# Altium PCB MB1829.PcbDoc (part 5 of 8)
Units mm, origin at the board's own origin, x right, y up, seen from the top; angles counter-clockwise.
Board outline 90 x 110 mm, 6 copper layers (Top Layer, Signal Layer 1, Signal Layer 2, Signal Layer 3, Signal Layer 4, Bottom Layer), stack 1.578 mm thick; 466 components, 354 nets, 2058 pads, 1522 vias.
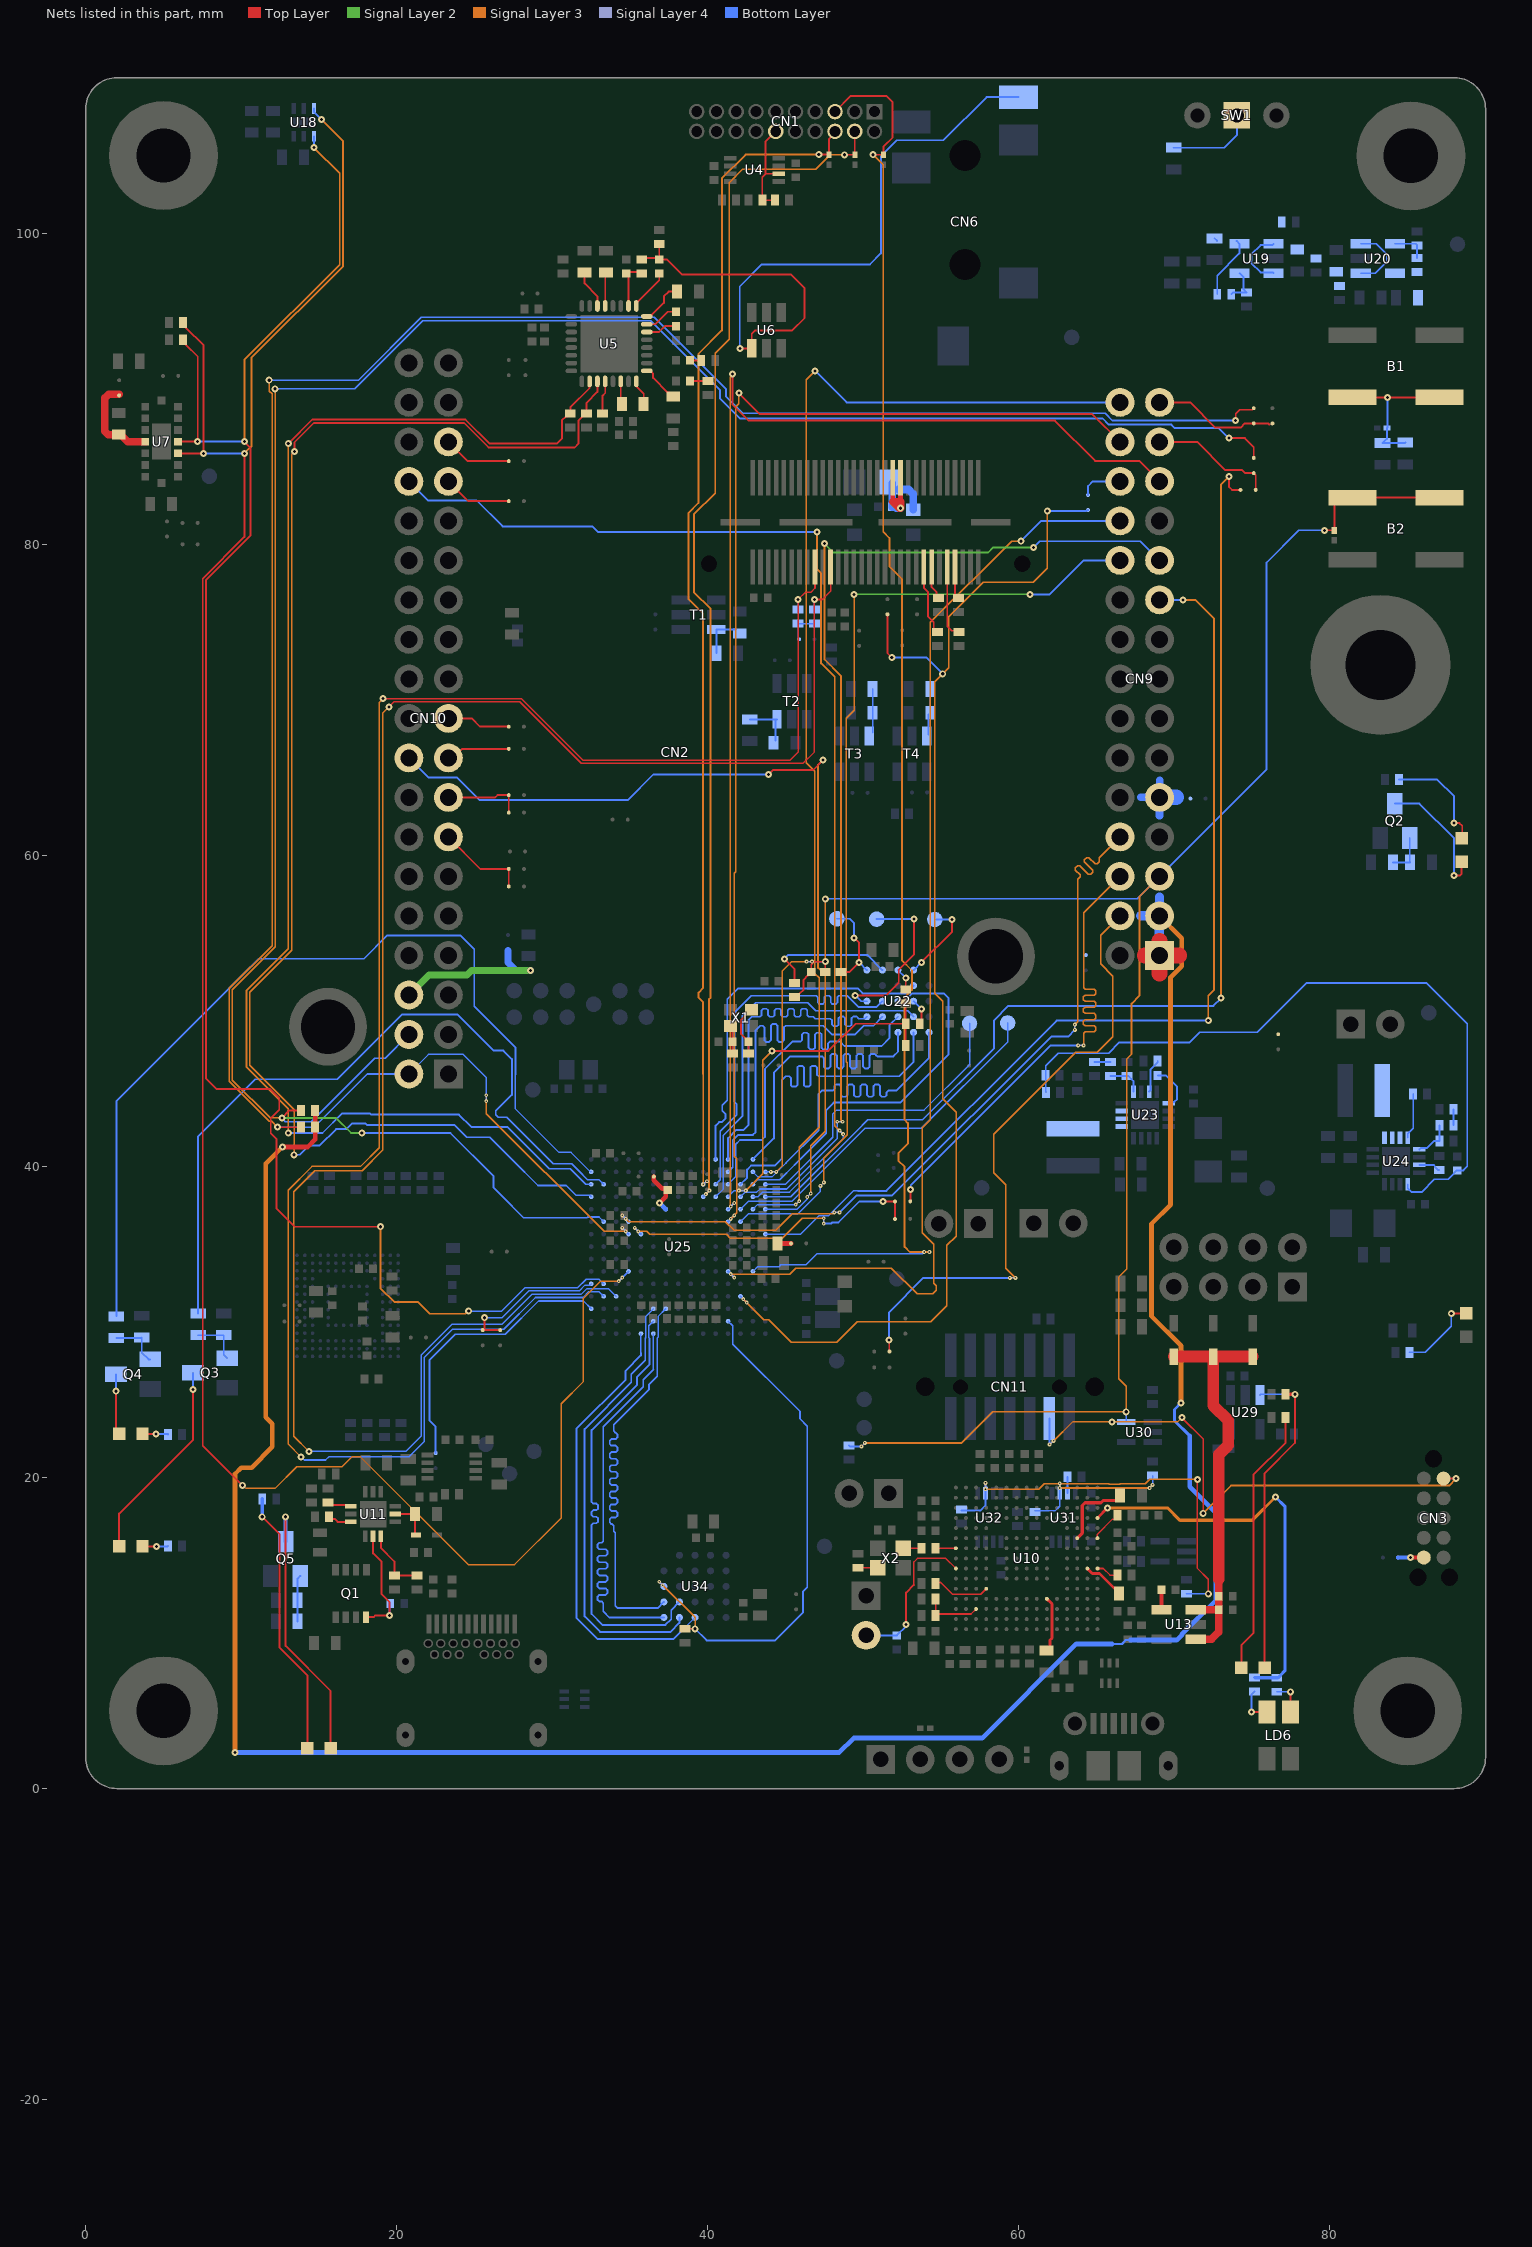
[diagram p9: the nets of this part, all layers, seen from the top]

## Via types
v1: diameter 0.45, hole 0.2, Top Layer to Bottom Layer, tented both sides, 1062 vias
v2: diameter 0.25, hole 0.1, Signal Layer 4 to Bottom Layer, tented both sides, 274 vias
v3: diameter 0.25, hole 0.1, Signal Layer 3 to Signal Layer 4, tented both sides, 119 vias
v4: diameter 0.25, hole 0.1, Top Layer to Signal Layer 1, tented both sides, 47 vias
v5: diameter 0.25, hole 0.1, Signal Layer 1 to Signal Layer 2, tented both sides, 20 vias

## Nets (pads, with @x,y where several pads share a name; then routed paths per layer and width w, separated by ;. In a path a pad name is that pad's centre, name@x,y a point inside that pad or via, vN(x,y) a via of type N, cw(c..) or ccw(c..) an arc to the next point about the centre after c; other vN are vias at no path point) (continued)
HEXASPI1.IO11: U25.G13 U34.A4 | length 28.8
  Bottom Layer w0.1: 36.75,26.525 36.75,28.975 36.8,29.025 36.8,30.35 U25.G13@37.3,30.85
  Bottom Layer w0.12: 33.95,16.585 33.95,16.555 34.05,16.455 34.05,11.75 34.2,11.6 36.775,11.6 U34.A4@37.175,12 ; 33.95,16.59 33.95,16.905 33.845,17.01 33.8,17.01 33.695,17.115 33.695,17.325 33.8,17.43 33.95,17.43 34.075,17.43 34.18,17.535 34.18,17.745 34.075,17.85 33.95,17.85 33.8,17.85 33.695,17.955 33.695,18.165 33.8,18.27 33.95,18.27 34.075,18.27 34.18,18.375 34.18,18.585 34.075,18.69 33.95,18.69 33.8,18.69 33.695,18.795 33.695,19.005 33.8,19.11 33.95,19.11 34.075,19.11 34.18,19.215 34.18,19.425 34.075,19.53 33.95,19.53 33.8,19.53 33.695,19.635 33.695,19.845 33.8,19.95 33.95,19.95 34.075,19.95 34.18,20.055 34.18,20.265 34.075,20.37 33.95,20.37 33.8,20.37 33.695,20.475 33.695,20.685 33.8,20.79 33.95,20.79 34.075,20.79 34.18,20.895 34.18,21.105 34.075,21.21 33.95,21.21 33.8,21.21 33.695,21.315 33.695,21.525 33.8,21.63 33.95,21.63 34.075,21.63 34.18,21.735 34.18,21.945 34.075,22.05 33.95,22.05 33.8,22.05 33.695,22.155 33.695,22.365 33.8,22.47 33.95,22.47 34.075,22.47 34.18,22.575 34.18,22.785 34.075,22.89 34.055,22.89 33.95,22.995 33.95,23.1 33.95,23.4 36.225,25.675 36.225,26 36.75,26.525
HEXASPI1.IO12: U25.F15 U34.A5 | length 27.8
  Bottom Layer w0.1: 36.5,26.925 U25.F15@36.5,29.25
  Bottom Layer w0.12: 36.5,26.925 35.85,26.275 35.85,25.85 33.275,23.275 33.275,16.45 33.275,15.915 33.17,15.81 33.02,15.81 32.915,15.705 32.915,15.495 33.02,15.39 33.275,15.39 33.439,15.39 33.544,15.285 33.544,15.075 33.439,14.97 33.275,14.97 33.02,14.97 32.915,14.865 32.915,14.655 33.02,14.55 33.275,14.55 33.439,14.55 33.544,14.445 33.544,14.235 33.439,14.13 33.275,14.13 33.02,14.13 32.915,14.025 32.915,13.815 33.02,13.71 33.275,13.71 33.439,13.71 33.544,13.605 33.544,13.395 33.439,13.29 33.275,13.29 33.02,13.29 32.915,13.185 32.915,12.975 33.02,12.87 33.275,12.87 33.439,12.87 33.544,12.765 33.544,12.555 33.439,12.45 33.275,12.45 33.02,12.45 32.915,12.345 32.915,12.135 33.02,12.03 33.17,12.03 33.275,11.925 33.275,11.61 33.275,11.4 33.675,11 U34.A5@37.175,11
HEXASPI1.IO13: U25.F14 U34.B4 | length 28.6
  Bottom Layer w0.1: 36.25,27.275 36.25,28.95 36.2,29 36.2,29.75 U25.F14@36.5,30.05
  Bottom Layer w0.12: 36.25,27.275 35.45,26.475 35.45,25.975 32.525,23.05 32.525,18.95 32.525,18.74 32.525,18.425 32.63,18.32 32.836,18.32 32.941,18.215 32.941,18.005 32.836,17.9 32.63,17.9 32.525,17.795 32.525,17.585 32.63,17.48 32.836,17.48 32.941,17.375 32.941,17.165 32.836,17.06 32.63,17.06 32.525,16.955 32.525,16.7 32.525,11.225 33.225,10.525 37.275,10.525 37.65,10.9 37.65,11.475 U34.B4@38.175,12
HEXASPI1.IO14: U25.F13 U34.B5 | length 28.7
  Bottom Layer w0.1: 35.975,27.55 35.975,28.95 36,28.975 36,30.35 U25.F13@36.5,30.85
  Bottom Layer w0.12: 35.975,27.55 35.076,26.651 35.076,26.112 32.075,23.111 32.075,11.075 33.075,10.075 37.6,10.075 38.175,10.65 U34.B5@38.175,11
HEXASPI1.IO15: U25.E15 U34.C5 | length 28.7
  Bottom Layer w0.1: 35.7,28.025 U25.E15@35.7,29.25
  Bottom Layer w0.12: 35.7,28.025 35.7,27.85 34.713,26.863 34.713,26.288 31.55,23.125 31.55,10.975 32.9,9.625 37.8,9.625 U34.C5@39.175,11
HEXASPI1.NCS: R52.1 U25.M14 U34.A3 | length 34
  Top Layer w0.12: R52.1@38.525,10.275 v1(39.175,10.275)
  Signal Layer 3 w0.09: v3(37.1,13.075) 39.175,11 v1(39.175,10.275)
  Signal Layer 4 w0.1: v2(36.875,13.3) v3(37.1,13.075)
  Bottom Layer w0.1: U25.M14@41.3,30.05 41.6,29.75 41.6,28.575
  Bottom Layer w0.12: v2(36.875,13.3) U34.A3@37.175,13 ; v1(39.175,10.275) 39.925,9.525 44.338,9.525 46.115,11.302 46.115,12.66 46.39,12.935 46.39,23.31 45.925,23.775 45.925,24.25 41.6,28.575
I2C1.SCL: CN10.2 R29.1 SB7.1 U25.D7 | length 152
  Top Layer w0.09: v1(12.325,42.525) R29.1@13.85,42.525 ; v1(73.925,87.95) 73.945,87.97 73.945,88.395 74.2,88.65 74.994,88.65 75.094,88.75 SB7.1@75.1,88.75
  Signal Layer 3 w0.09: v1(11.8,90.55) 11.805,90.545 11.805,89.847 11.985,89.667 11.985,54.204 9.235,51.454 9.235,45.471 11.812,42.894 11.956,42.894 v1(12.325,42.525) ; v3(25.75,44.2) 25.75,43.4 33.325,35.825 v3(34.725,35.825)
  Signal Layer 4 w0.1: v3(25.75,44.2) v2(25.75,44.575) ; v2(34.5,36.05) v3(34.725,35.825)
  Bottom Layer w0.1: v1(12.325,42.525) 14.675,42.525 18.094,45.944 CN10.2@20.78,45.944 22.036,47.2 24.266,47.2 25.75,45.716 v2(25.75,44.575)
  Bottom Layer w0.12: v1(11.8,90.55) 17.539,90.55 21.584,94.595 36.564,94.595 41.175,89.984 41.175,89.502 42.253,88.424 65.544,88.424 66.018,87.95 v1(73.925,87.95) ; v2(34.5,36.05) U25.D7@34.9,35.65
I2C1.SDA: CN10.4 R28.1 SB8.1 U25.B6 | length 154.9
  Top Layer w0.12: v1(12.625,43.125) 13.1,43.6 R28.1@13.85,43.6 ; v1(73.5,86.825) 74.525,86.825 75.1,86.25 SB8.1@75.1,85.55
  Signal Layer 2 w0.12: v1(12.625,43.125) 16.088,43.125 17.063,42.15 v1(17.75,42.15)
  Signal Layer 3 w0.09: v1(12.175,90) 12.175,54.125 9.425,51.375 9.425,45.55 11.85,43.125 v1(12.625,43.125)
  Bottom Layer w0.1: 27.425,37.431 28.156,36.7 32.225,36.7 32.275,36.75 33,36.75 U25.B6@33.3,36.45
  Bottom Layer w0.12: v1(12.175,90) 17.3,90 21.675,94.375 36.325,94.375 40.775,89.925 40.775,89.391 42.066,88.1 65.375,88.1 65.775,87.7 69.8,87.7 70.025,87.475 72.85,87.475 v1(73.5,86.825) ; v1(12.625,43.125) 12.625,43.075 12.825,42.875 14.5,42.875 18.585,46.96 19.256,46.96 CN10.4@20.78,48.484 ; v1(17.75,42.15) 23.45,42.15 26.225,39.375 26.225,38.631 27.425,37.431
I2C3.SCL: R8.1 U7.C4 U18.1 U25.B11 | length 116.3
  Top Layer w0.12: U7.C4@5.925,86.6 v1(7.2,86.6) 7.2,92.075 6.445,92.83 6.445,92.955 R8.1@6.25,93.15 ; v1(10.2,86.6) 10.585,86.215 10.585,80.549 7.745,77.709 7.745,45.647 8.417,44.975 11.861,44.975 12.441,44.396 12.441,43.641 11.9,43.1 11.9,42.125 12.255,41.77 12.255,37.298 13.428,36.125 v1(18.95,36.125)
  Signal Layer 3 w0.12: v1(10.2,86.6) 10.2,91.853 16.33,97.983 16.33,103.855 v1(14.675,105.51) ; v1(18.95,36.125) 18.95,32.184 19.859,31.275 21.375,31.275 22.125,30.525 24.39,30.525 24.565,30.7 v1(24.625,30.7)
  Bottom Layer w0.1: v1(24.625,30.7) 26.75,30.7 28.25,32.2 31.625,32.2 32.175,32.75 33,32.75 U25.B11@33.3,32.45
  Bottom Layer w0.12: v1(7.2,86.6) v1(10.2,86.6) ; v1(14.675,105.51) U18.1@14.675,106.235
I2C3.SDA: R7.1 U7.C3 U18.6 U25.D10 | length 151.2
  Top Layer w0.12: U7.C3@5.925,85.85 v1(7.575,85.85) 7.575,86.431 7.585,86.441 7.585,92.79 6.445,93.93 6.445,94.055 R7.1@6.25,94.25 ; v1(10.075,19.5) 7.525,22.05 7.525,77.8 10.2,80.475 v1(10.2,85.85)
  Signal Layer 3 w0.1: v1(10.075,19.5) 10.109,19.5 10.309,19.3 12.175,19.3 13.575,20.7 16.475,20.7 17.1,21.325 17.675,21.325 24.6,14.4 27.575,14.4 30.575,17.4 30.575,24.75 32.003,26.178 32.003,31.52 32.95,32.467 32.95,32.474 33.101,32.625 v3(34.275,32.625)
  Signal Layer 3 w0.12: v1(10.2,85.85) 10.65,86.3 10.65,91.992 16.55,97.892 16.55,105.925 v1(15.15,107.325)
  Signal Layer 4 w0.1: v3(34.275,32.625) v2(34.5,32.85)
  Bottom Layer w0.12: v1(7.575,85.85) v1(10.2,85.85) ; U18.6@14.675,108.015 14.675,107.8 v1(15.15,107.325) ; v2(34.5,32.85) U25.D10@34.9,33.25
I2C4.SCL: R14.1 U5.3 U25.A4 | length 94.2
  Top Layer w0.12: v1(13.425,85.975) 13.425,86.564 14.661,87.8 24.328,87.8 25.903,86.225 31.43,86.225 31.675,86.47 31.675,87.95 31.917,88.192 31.917,88.205 32.112,88.4 R14.1@32.207,88.4 32.207,89.1 ; 32.203,89.103 32.9,89.8 U5.3@32.9,90.475
  Signal Layer 3 w0.12: v1(13.4,40.75) 13.41,40.76 13.41,43.64 10.55,46.5 10.55,51.2 13.245,53.895 13.245,85.795 v1(13.425,85.975)
  Bottom Layer w0.1: 27.425,40.425 29.075,38.775 30.9,38.775 31.525,38.15 32.4,38.15 U25.A4@32.5,38.05
  Bottom Layer w0.12: v1(13.4,40.75) 13.775,40.75 14.375,41.35 15.047,41.35 16.102,42.405 16.744,42.405 16.808,42.468 16.818,42.468 17.105,42.755 18.001,42.755 18.081,42.675 23.689,42.675 24.484,41.88 25.97,41.88 27.425,40.425
I2C4.SDA: R13.1 U5.2 U25.A3 | length 91.9
  Top Layer w0.12: v1(13.025,86.475) 14.575,88.025 24.415,88.025 25.965,86.475 30.3,86.475 30.619,86.794 30.619,87.969 30.855,88.205 30.955,88.205 R13.1@31.15,88.4 31.165,88.415 31.165,88.815 32.4,90.05 U5.2@32.4,90.475
  Signal Layer 3 w0.12: v1(13.025,42.15) 13.025,43.7 10.775,45.95 10.775,45.964 10.33,46.409 10.33,51.291 13.025,53.986 v1(13.025,86.475)
  Bottom Layer w0.1: 27.425,42.225 29.8,39.85 31.15,39.85 32.15,38.85 U25.A3@32.5,38.85
  Bottom Layer w0.12: v1(13.025,42.15) 15.225,42.15 16.49,43.415 18.274,43.415 18.354,43.335 23.99,43.335 24.785,42.54 27.11,42.54 27.425,42.225
I2C5.SCL: CN2.44 R70.2 U25.B12 | length 122.5
  Top Layer w0.1: v1@19.125,70.079 27.996,70.079 31.95,66.125 45.3,66.125 45.8,66.625 v1(45.8,76.45) 46.275,76.925 46.625,76.925 46.889,77.189 CN2.44@46.889,78.54
  Signal Layer 3 w0.1: v1(13.85,21.325) 13.025,22.15 13.025,38.475 14.55,40 17.675,40 18.88,41.205 18.88,69.83 v1(19.125,70.075)
  Bottom Layer w0.1: v1(13.85,21.325) 14.05,21.125 15.425,21.125 15.625,21.325 20.775,21.325 21.76,22.31 21.76,27.71 23.575,29.525 26.87,29.525 28.92,31.575 31.975,31.575 32.35,31.95 33,31.95 U25.B12@33.3,31.65 ; R70.2@45.8,75.796 v1(45.8,76.45)
I2C5.SDA: CN2.40 R69.2 U25.C12 | length 122.6
  Top Layer w0.1: v1(19.5,69.55) 19.829,69.879 27.913,69.879 31.867,65.925 46.125,65.925 46.85,66.65 v1(46.85,76.45) 47.35,76.45 47.889,76.989 CN2.40@47.889,78.54
  Signal Layer 3 w0.1: v1(14.353,21.675) 13.375,22.653 13.375,38.375 14.725,39.725 17.775,39.725 19.1,41.05 19.1,69.15 v1(19.5,69.55)
  Bottom Layer w0.1: v1(14.353,21.675) 20.575,21.675 21.56,22.66 21.56,27.86 23.55,29.85 26.76,29.85 28.685,31.775 31.85,31.775 32.225,32.15 32.45,32.15 33.6,32.15 U25.C12@34.1,31.65 ; R69.2@46.85,75.796 v1(46.85,76.45)
IOREF: CN9.3 R28.2 R29.2 SB56.2 | length 163.3
  Top Layer w0.3: v1(12.64,41.25) 14.265,41.25 14.75,41.735 R29.2@14.75,42.525 R28.2@14.75,43.6
  Signal Layer 3 w0.3: v1(9.6,2.325) 9.6,20.225 10.008,20.633 10.662,20.633 12,21.971 12,23.45 11.575,23.875 11.575,40.185 v1(12.64,41.25) ; CN9.3@69.04,56.104 70.47,54.674 70.47,52.875 69.75,52.155 69.75,37.55 68.525,36.325 68.525,30.375 70.425,28.475 v1(70.425,24.8)
  Bottom Layer w0.15: 66,9.3 66.625,9.3 66.875,9.55 67.175,9.55
  Bottom Layer w0.2: v1(70.425,24.8) 70,24.375 70,23.65 70.975,22.675
  Bottom Layer w0.3: v1(9.6,2.325) 48.45,2.325 49.375,3.25 57.633,3.25 63.683,9.3 66,9.3 ; 67.175,9.55 70.15,9.55 70.5,9.9 ; v1(70.425,24.8) v1@70.425,24.825 ; 70.475,9.925 72.675,12.125 72.675,17.7 70.975,19.4 70.975,22.675
  Bottom Layer w0.6: 67.825,56.125 69.019,56.125 CN9.3@69.04,56.104 ; 69.019,54.91 CN9.3@69.019,56.104 ; CN9.3@69.04,56.125 69.04,57.319
IOVDD_TOF_SENSOR: C18.1 SB5.2 U7.A4 | length 6
  Top Layer w0.5: SB5.2@2.15,89.65 1.475,89.65 1.225,89.4 1.225,87.275 1.45,87.05 2.25,87.05 2.7,86.6 U7.A4@3.825,86.6
LED_GREEN: R107.1 U25.A2 | length 59.5
  Bottom Layer w0.1: 27.625,45.925 27.625,43.7 30.425,40.9 31.209,40.9 32.459,39.65 U25.A2@32.5,39.65
  Bottom Layer w0.12: R107.1@1.972,30.366 1.972,44.191 11.131,53.35 17.892,53.35 19.392,54.85 24.084,54.85 24.978,53.957 24.978,50.298 27.635,47.64 27.635,45.935 27.625,45.925
LED_RED: R105.1 U25.B3 | length 48.8
  Bottom Layer w0.1: 31.944,39.47 32.265,39.15 33,39.15 U25.B3@33.3,38.85
  Bottom Layer w0.12: R105.1@7.225,30.55 7.225,41.94 10.891,45.606 16.173,45.606 20.342,49.775 23.9,49.775 26.225,47.45 26.85,47.45 27.4,46.9 27.4,44.603 26.365,43.568 26.365,43.332 26.532,43.165 27.085,43.165 30.075,40.175 31.24,40.175 31.944,39.47
LED_STLK: R130.2 R131.2 U10.D15 | length 26.3
  Top Layer w0.2: U10.D15@65.05,17.4 v1(65.7,18.05)
  Signal Layer 3 w0.2: v1(65.7,18.05) 69.55,18.05 70.35,17.25 75,17.25 v1(76.5,18.75)
  Bottom Layer w0.2: R130.2@75.15,7.15 75.175,7.125 76.67,7.125 76.825,7.28 76.825,7.3 77.1,7.575 77.1,18.15 v1(76.5,18.75)
MEMS_LED: CN1.12 R2.2 R3.2 U4.2 | length 6.5
  Top Layer w0.12: R3.2@44.325,102.125 R2.2@43.5,102.125 43.5,103.604 43.7,103.804 ; CN1.12@44.365,106.55 43.7,105.885 43.7,103.804 ; U4.2@44.55,103.825 43.721,103.825 43.7,103.804
MIC: C6.1 CN6.2 R4.2 R6.1 U6.4 | length 50.2
  Top Layer w0.12: R6.1@35.75,98.4 36.875,98.4 R4.2@36.875,99.3 ; C6.1@36.875,98.3 37.375,98.3 38.325,97.35 45.325,97.35 46.225,96.45 46.225,94.55 45.428,93.753 43.053,93.753 42.825,93.525 42.825,93.425 ; v1(42.055,92.6) U6.4@42.825,92.6 42.825,93.425
  Bottom Layer w0.12: v1(42.055,92.6) 42.055,94.545 42.05,94.55 42.05,96.575 43.475,98 50.425,98 51.125,98.7 51.125,104.95 52.15,105.975 55.15,105.975 57.925,108.75 CN6.2@59.975,108.75
MIC.CCK0: CN1.4 U2.1 U25.K4 | length 77.7
  Top Layer w0.12: v1(48.779,105.046) U2.1@49.441,105.046 ; CN1.4@49.445,106.55 49.445,105.043 U2.1@49.45,105.037
  Signal Layer 3 w0.1: v3(39.875,38.225) 40.075,38.425 40.075,45.925
  Signal Layer 3 w0.12: 40.075,45.925 40.075,50.763 40.172,50.861 40.172,75.853 39.108,76.917 39.108,81.922 40.475,83.289 40.475,92.275 41.375,93.175 41.375,103.261 42.229,104.115 46.926,104.115 47.857,105.046 v1(48.779,105.046)
  Signal Layer 4 w0.1: v3(39.875,38.225) v2(40.1,38.45)
  Bottom Layer w0.12: U25.K4@39.7,38.05 v2(40.1,38.45)
MIC.SDIN0: CN1.6 U1.1 U25.K3 | length 76.1
  Top Layer w0.12: v1(47.131,105.056) U1.1@47.794,105.056 ; U1.1@47.8,105.037 47.8,106.063 48.175,106.438 CN1.6@48.175,106.55
  Signal Layer 3 w0.1: v3(39.7,38.85) 39.7,45.925
  Signal Layer 3 w0.12: 39.7,45.925 39.7,50.563 39.402,50.861 39.402,51.179 39.7,51.477 39.7,75.548 38.75,76.497 38.75,82.012 39.4,82.662 39.4,92.25 40.9,93.75 40.9,103.525 42.431,105.056 v1(47.131,105.056)
  Signal Layer 4 w0.1: v3(39.7,38.85) 39.723,38.85 39.924,39.051 v2(39.947,39.051)
  Bottom Layer w0.1: v3(39.7,38.85) 39.723,38.85 39.924,39.051 v2(39.947,39.051)
MIC.SDIN4: CN1.5 U3.1 U25.P10 | length 94.2
  Top Layer w0.12: CN1.5@48.175,107.82 49.19,108.835 51.466,108.835 51.875,108.426 51.875,106.156 51.3,105.581 U3.1@51.3,105.037 51.287,105.05 v1(50.625,105.05)
  Signal Layer 3 w0.12: v1(50.625,105.05) 51.28,104.395 51.28,80.8 51.675,80.406 51.675,78.584 52.475,77.784 52.475,53.248 53.125,52.598 53.125,51.35 52.652,50.877 52.652,43 52.864,42.789 52.864,41.464 52.25,40.85 52.25,40.379 52.65,39.979 52.65,34.83 52.98,34.5 v3(54.248,34.5)
  Signal Layer 4 w0.1: v2(53.9,34.5) v3(54.248,34.5)
  Bottom Layer w0.1: U25.P10@42.9,33.25 43.2,33.55 44.567,33.55 44.692,33.675 46.309,33.675 47.034,34.4 50.796,34.4 53.8,34.4 v2(53.9,34.5)
NetB1_1: B1.1 B1.2 R67.2 R68.2 U21.1 | length 10.1
  Top Layer w0.12: B1.2@81.45,89.45 v1(83.688,89.45) B1.1@87.05,89.45
  Bottom Layer w0.12: R68.2@83.375,86.515 R68.2@83.402,86.515 ; v1(83.688,89.45) 83.688,87.501 U21.1@83.662,87.475 83.662,86.775 R68.2@83.402,86.515 ; R67.2@84.85,86.54 84.825,86.515 R68.2@83.402,86.515
NetC3_2: C3.2 U5.22 | length 2.5
  Top Layer w0.12: C3.2@32.075,97.475 32.075,96.775 32.9,95.95 U5.22@32.9,95.325
NetC4_2: C4.2 U5.21 | length 2.2
  Top Layer w0.12: U5.21@33.4,95.325 33.4,97.425 C4.2@33.45,97.475
NetC5_2: C5.2 R6.2 U5.18 | length 3.2
  Top Layer w0.12: U5.18@34.9,95.325 34.9,97.35 34.75,97.5 R6.2@35.75,97.5
NetC6_2: C6.2 U5.17 | length 2.8
  Top Layer w0.12: U5.17@35.4,95.325 35.4,95.5 36.875,96.975 C6.2@36.875,97.5
NetC7_2: C7.2 U5.16 | length 2.9
  Top Layer w0.12: U5.16@36.075,94.65 36.3,94.65 37.175,95.525 37.175,95.95 37.475,96.25 C7.2@38.025,96.25
NetC9_2: C9.2 U5.15 | length 2.2
  Top Layer w0.12: U5.15@36.075,94.15 36.625,94.15 37.425,94.95 C9.2@37.95,94.95
NetC10_2: C10.2 U5.14 | length 2
  Top Layer w0.12: U5.14@36.075,93.65 36.85,93.65 37.225,94.025 C10.2@37.95,94.025
NetC14_1: C14.1 R10.2 | length 0.8
  Top Layer w0.12: C14.1@38.825,91.825 R10.2@39.575,91.825
NetC15_1: C15.1 R11.2 | length 1.2
  Top Layer w0.12: C15.1@38.825,90.5 R11.2@40,90.5
NetC16_2: C16.2 U5.9 | length 2.5
  Top Layer w0.12: U5.9@36.075,91.15 36.3,91.15 36.48,90.97 36.48,90.695 37.425,89.75 37.525,89.75 C16.2@37.775,89.5
NetC17_1: C17.1 U5.8 | length 1.6
  Top Layer w0.12: U5.8@35.4,90.475 35.4,90.15 35.875,89.675 C17.1@35.875,89.025
NetC17_2: C17.2 U5.6 | length 1.5
  Top Layer w0.12: U5.6@34.4,90.475 34.4,89.1 C17.2@34.475,89.025
NetC32_1: C32.1 R27.2 X1.3 | length 1.8
  Top Layer w0.12: X1.3@41.45,49.025 41.575,48.9 C32.1@41.575,48.025 R27.2@41.575,47.25
NetC33_1: C33.1 R26.2 X1.1 | length 3.3
  Top Layer w0.12: R26.2@42.625,47.25 C33.1@42.625,48.025 42.125,48.525 42.125,49.4 X1.1@42.8,50.075
NetC38_2: C38.2 SB32.2 U25.G5 | length 2.9
  Top Layer w0.3: SB32.2@36.525,39.35 36.525,39.114 37.059,38.58 37.295,38.58 37.295,38.045 v1@36.9,37.65
  Bottom Layer w0.3: v1(36.9,37.65) U25.G5@37.3,37.25
NetC78_2: C78.2 U10.F13 | length 5.1
  Top Layer w0.2: U10.F13@63.75,16.1 64.075,16.425 64.075,18.2 64.25,18.375 65.275,18.375 65.425,18.525 66.5,18.525 C78.2@66.5,18.85
NetC81_2: C81.2 D4.2 U11.8 | length 2.6
  Top Layer w0.12: U11.8@19.9,17.65 C81.2@21.175,17.65 21.175,16.35 D4.2@21.225,16.3
NetC95_2: C95.2 U10.J14 | length 2.8
  Top Layer w0.2: U10.J14@64.4,14.15 64.725,13.825 65.15,13.825 65.185,13.825 66.115,12.895 66.205,12.895 66.425,12.675 C95.2@66.425,12.55
NetC96_2: C96.2 U13.4 | length 1.3
  Top Layer w0.25: U13.4@69.175,11.5 C96.2@69.175,12.775
NetC98_2: C98.2 C100.2 D1.2 D2.2 D3.2 U13.1 U13.3 | length 26.6
  Top Layer w0.5: U13.1@71.375,9.6 72.375,9.6 72.85,10.075 C100.2@72.85,11.5 ; U13.3@71.375,11.5 C100.2@72.85,11.5 ; 72.85,13.45 C98.2@72.85,12.375 C100.2@72.85,11.5
  Top Layer w0.75: D2.2@69.95,27.78 D1.2@72.5,27.78 ; 72.85,13.45 72.85,21.475 73.45,22.075 73.45,23.675 72.5,24.625 D1.2@72.5,27.78 ; D3.2@75.025,27.78 D1.2@72.5,27.78
NetC110_2: C110.2 U10.M10 | length 3.6
  Top Layer w0.2: C110.2@61.775,8.85 62,9.075 62,9.55 62.125,9.675 62.125,11.875 U10.M10@61.8,12.2
NetC115_2: C115.2 R57.2 R61.2 U19.1 U19.3 | length 4
  Bottom Layer w0.12: U19.3@76.375,97.425 76.317,97.483 75.542,97.483 74.95,98.075 74.95,98.65 75.542,99.242 76.292,99.242 U19.1@76.375,99.325
NetC116_2: C116.2 R63.2 U20.1 U20.3 | length 4.4
  Bottom Layer w0.12: U20.1@81.975,97.425 82.9,97.425 83.65,98.175 83.65,98.65 82.975,99.325 U20.3@81.975,99.325
NetC119_1: C119.1 C120.2 CN2.21 CN2.23 L4.2 | length 8.4
  Top Layer w0.3: 51.885,82.738 CN2.23@51.885,84.097 ; 52.385,82.738 CN2.21@52.385,84.097
  Top Layer w0.5: 51.885,82.738 52.385,82.738 52.385,82.33 v1(52.376,82.321) 52.301,82.321 51.885,82.738
  Bottom Layer w0.5: C119.1@51.85,83.921 C120.2@51.85,82.421 51.85,82.396 51.855,82.391 52.061,82.391 52.131,82.321 v1@52.35,82.321 ; C119.1@52.25,83.521 52.907,83.521 53.2,83.229 L4.2@53.2,82.225
NetC121_1: C121.1 R73.2 T1.3 | length 2.8
  Bottom Layer w0.12: R73.2@40.55,72.996 T1.3@40.55,74.521 C121.1@41.8,74.521
NetC122_1: C122.1 R74.2 T4.3 | length 2.8
  Bottom Layer w0.12: T4.3@54.175,67.771 C122.1@54.175,69.046 ; C122.1@54.3,69.171 R74.2@54.3,70.696
NetC123_1: C123.1 R75.2 T3.3 | length 2.8
  Bottom Layer w0.12: T3.3@50.6,67.896 C123.1@50.6,69.171 R75.2@50.6,70.696
NetC124_1: C124.1 R76.2 T2.3 | length 3
  Bottom Layer w0.12: R76.2@42.7,68.746 T2.3@44.45,68.746 ; C124.1@44.35,67.371 T2.3@44.35,68.646
NetC126_2: C126.2 U23.9 | length 3
  Bottom Layer w0.12: C126.2@68.922,45.841 69.463,45.841 70.172,45.132 70.172,44.333 69.993,44.154 69.712,44.154 U23.9@69.622,44.064
NetC147_1: C147.1 Q1.4 U11.5 | length 7.9
  Top Layer w0.12: Q1.4@18.025,11.025 18.513,11.025 18.625,11.138 v1(19.525,11.138) 19.525,12 19.025,12.5 19.025,14.575 18.475,15.125 U11.5@18.475,16.225
  Bottom Layer w0.12: v1(19.525,11.138) 19.525,11.847 C147.1@19.578,11.9
NetC148_1: C148.1 JP6.2 U10.J1 | length 10.2
  Top Layer w0.1: 53.25,13.1 53.25,14.575 53.475,14.8 55.3,14.8 U10.J1@55.95,14.15
  Top Layer w0.12: v1(52.75,10.55) 52.75,12.6 53.25,13.1
  Bottom Layer w0.12: JP6.2@50.175,9.855 50.18,9.85 C148.1@52.15,9.85 52.75,10.45 v1(52.75,10.55)
NetC149_2: C149.2 R85.1 R87.1 U24.9 | length 46.2
  Bottom Layer w0.12: R87.1@61.747,44.766 61.722,44.791 R85.1@61.722,45.866 61.722,46.478 62.519,47.275 65.761,47.275 66.461,47.975 70.975,47.975 71.625,48.625 75.325,48.625 78.5,51.8 86.2,51.8 88.825,49.175 88.825,39.999 88.576,39.75 88.15,39.75 87.955,39.555 87.955,39.53 87.6,39.175 86.706,39.175 85.886,38.355 85.249,38.355 85.094,38.51 85.09,38.51 85,38.6 U24.9@85,38.85
NetCN2_8: CN2.8 R17.1 | length 2.1
  Top Layer w0.12: CN2.8@55.889,78.54 55.889,76.745 56.084,76.55 R17.1@56.125,76.55
NetCN2_10: CN2.10 R18.1 | length 4.7
  Top Layer w0.12: CN2.10@55.389,78.54 55.389,74.744 55.69,74.443 56.082,74.443 R18.1@56.15,74.375
NetCN2_14: CN2.14 R16.1 | length 2.2
  Top Layer w0.12: CN2.14@54.389,78.54 54.389,77.236 54.71,76.915 54.71,76.665 R16.1@54.825,76.55
NetCN2_16: CN2.16 R19.1 | length 4.6
  Top Layer w0.12: CN2.16@53.889,78.54 53.889,77.211 54.15,76.95 54.15,75.375 54.525,75 54.525,74.545 54.72,74.35 R19.1@54.775,74.35
NetCN3_5: CN3.5 SB61.2 | length 1.7
  Top Layer w0.25: v1(85.175,14.855) CN3.5@86.03,14.855
  Bottom Layer w0.25: SB61.2@84.375,14.85 84.727,14.85 84.732,14.855 v1(85.175,14.855)
NetCN9_1: CN9.1 SB26.2 | length 4.3
  Top Layer w1: 68.089,53.564 CN9.1@69.04,53.564 ; 69.04,52.405 CN9.1@69.04,53.564 ; 69.04,54.5 CN9.1@69.04,53.564 ; 70.296,53.564 CN9.1@69.04,53.564
NetCN9_4: CN9.4 SB45.1 | length 40.2
  Top Layer w0.12: v1(51.65,28.85) 51.663,28.837 51.663,28.113 SB45.1@51.675,28.1
  Signal Layer 3 w0.09: v3(59.77,32.83) 59.155,33.445 59.155,38.835 58.385,39.605 58.385,42.065 63.655,47.335 65.035,47.335 66.045,48.345 66.045,52.24 65.26,53.025 65.26,54.864 CN9.4@66.5,56.104
  Signal Layer 4 w0.1: v2(59.42,32.83) v3(59.77,32.83)
  Bottom Layer w0.12: v1(51.65,28.85) 51.65,30.625 53.855,32.83 v2(59.42,32.83)
NetCN9_6: CN9.6 SB33.1 | length 33
  Top Layer w0.12: SB33.1@53.013,37.75 53.024,37.761 53.024,38.499 v1(53.035,38.51)
  Signal Layer 3 w0.09: v3(64.157,47.783) 64.157,48.131 64.157,48.566 64.255,48.664 64.834,48.664 64.931,48.761 64.931,48.956 64.834,49.054 64.25,49.054 64.152,49.151 64.152,49.346 64.25,49.444 64.834,49.444 64.931,49.541 64.931,49.736 64.834,49.834 64.25,49.834 64.152,49.931 64.152,50.126 64.25,50.224 64.834,50.224 64.931,50.321 64.931,50.516 64.834,50.614 64.25,50.614 64.152,50.711 64.152,50.906 64.25,51.004 64.834,51.004 64.931,51.101 64.931,51.296 64.834,51.394 64.255,51.394 64.157,51.491 64.157,51.95 64.157,56.301 CN9.6@66.5,58.644
  Signal Layer 4 w0.1: v2(63.81,47.783) v3(64.157,47.783)
  Bottom Layer w0.12: v1(53.035,38.51) 53.045,38.52 53.045,38.795 62.033,47.783 v2(63.81,47.783)
NetCN9_9: CN9.9 SB54.2 | length 4.6
  Top Layer w0.7: CN9.9@69.04,63.724 CN9.9@69.114,63.651
  Bottom Layer w0.5: 67.85,63.734 CN9.9@69.04,63.734 ; 69.04,62.55 CN9.9@69.04,63.724 69.05,63.734 69.05,64.825
  Bottom Layer w1: CN9.9@69.05,63.724 70.125,63.724
NetCN9_26: CN9.26 SB48.1 | length 2.7
  Bottom Layer w0.12: SB48.1@64.45,83.175 64.45,83.75 64.744,84.044 CN9.26@66.5,84.044
NetCN9_27: CN9.27 SB8.2 SB9.2 | length 8
  Top Layer w0.12: CN9.27@69.04,86.584 71.466,86.584 73.275,84.775 74.35,84.775 74.55,84.575 SB8.2@75.1,84.575 75.1,84.561 75.225,84.436 SB9.2@75.225,83.5
NetCN9_29: CN9.29 SB6.2 SB7.2 | length 7.9
  Top Layer w0.12: CN9.29@69.04,89.124 71.001,89.124 72.625,87.5 74.25,87.5 74.525,87.775 SB7.2@75.1,87.775 76.025,87.775 76.103,87.697
NetCN10_6: CN10.6 SB55.1 | length 10.9
  Signal Layer 2 w0.45: CN10.6@20.78,51.024 22.07,52.314 24.509,52.314 24.795,52.6 v1(28.6,52.6)
  Bottom Layer w0.45: SB55.1@27.15,53.9 27.15,53.116 27.666,52.6 v1(28.6,52.6)
NetCN10_13: CN10.13 SB24.2 SB25.2 | length 5.9
  Top Layer w0.12: CN10.13@23.32,61.184 25.379,59.125 SB24.2@27.2,59.125 SB25.2@27.2,58
NetCN10_15: CN10.15 SB22.2 SB23.2 | length 5.1
  Top Layer w0.12: CN10.15@23.32,63.724 26.324,63.724 26.475,63.875 SB22.2@27.2,63.875 SB23.2@27.2,62.75
NetCN10_17: CN10.17 SB21.2 | length 4.1
  Top Layer w0.12: CN10.17@23.32,66.264 23.611,66.264 24.197,66.85 SB21.2@27.2,66.85
NetCN10_19: CN10.19 SB20.2 | length 4.1
  Top Layer w0.12: CN10.19@23.32,68.804 24.821,68.804 25.35,68.275 SB20.2@27.2,68.275
NetCN10_31: CN10.31 SB11.2 | length 4.4
  Top Layer w0.12: CN10.31@23.32,84.044 24.589,82.775 SB11.2@27.2,82.775
NetCN10_33: CN10.33 SB10.2 | length 4.4
  Top Layer w0.12: CN10.33@23.32,86.584 24.554,85.35 SB10.2@27.2,85.35
NetL2_1: L2.1 SB36.2 | length 0.9
  Top Layer w0.3: L2.1@44.475,35.05 SB36.2@45.35,35.05
NetL6_1: L6.1 U24.1 U24.2 U24.3
NetL7_1: L7.1 U23.1 U23.2 U23.3
NetLD1_1: LD1.1 R77.1 | length 7.2
  Top Layer w0.12: v1(87.975,62.075) 88.325,62.075 88.5,61.9 LD1.1@88.5,61
  Bottom Layer w0.12: R77.1@84.446,64.879 85.37,64.879 85.372,64.876 86.899,64.876 87.975,63.8 v1(87.975,62.075)
NetLD1_2: LD1.2 Q2.3 | length 8.4
  Top Layer w0.12: v1(87.975,58.7) 88.35,58.7 88.45,58.8 88.45,59.575 LD1.2@88.475,59.6
  Bottom Layer w0.12: Q2.3@84.175,63.325 85.75,63.325 87.975,61.1 v1(87.975,58.7)
NetLD2_1: LD2.1 R109.1 | length 5.2
  Top Layer w0.12: v1(87.8,30.55) LD2.1@88.75,30.55
  Bottom Layer w0.12: R109.1@85.1,28.05 86.131,28.05 87.8,29.719 v1(87.8,30.55)
NetLD3_1: LD3.1 R116.1 | length 1.7
  Top Layer w0.12: LD3.1@3.65,22.8 v1(4.525,22.8)
  Bottom Layer w0.12: v1(4.525,22.8) 5.275,22.8 R116.1@5.3,22.775
NetLD3_2: LD3.2 Q4.3 | length 3.9
  Top Layer w0.12: v1(1.95,25.55) 1.95,23 LD3.2@2.15,22.8
  Bottom Layer w0.12: Q4.3@1.947,26.641 1.947,25.553 v1(1.95,25.55)
NetLD4_1: LD4.1 R125.1 | length 1.7
  Top Layer w0.12: LD4.1@3.65,15.575 v1(4.55,15.575)
  Bottom Layer w0.12: v1(4.55,15.575) 5.275,15.575 R125.1@5.3,15.6
NetLD4_2: LD4.2 Q3.3 | length 13.1
  Top Layer w0.12: LD4.2@2.15,15.575 2.15,17.675 6.9,22.425 v1(6.9,25.65)
  Bottom Layer w0.12: v1(6.9,25.65) Q3.3@6.9,26.725
NetLD5_1: LD5.1 R34.1 | length 17.3
  Top Layer w0.12: LD5.1@74.3,7.775 74.3,9.225 75.075,10 75.075,20.175 77.15,22.25 R34.1@77.15,23.85
NetLD5_2: LD5.2 R33.1 U29.3 | length 21.3
  Top Layer w0.12: LD5.2@75.8,7.775 75.8,20.275 77.75,22.225 v1(77.75,25.35)
  Top Layer w0.2: R33.1@77.15,25.35 v1(77.75,25.35)
  Bottom Layer w0.12: U29.3@75.5,25.3 75.55,25.35 v1(77.75,25.35)
NetLD6_1: LD6.1 R130.1 | length 2.4
  Top Layer w0.12: v1@74.95,4.936 74.961,4.925 LD6.1@75.95,4.925
  Bottom Layer w0.12: v1(74.955,4.93) 74.955,6.055 R130.1@75.15,6.25
NetLD6_2: LD6.2 R131.1 | length 2.2
  Top Layer w0.12: LD6.2@77.45,4.925 v1(77.45,6.225)
  Bottom Layer w0.12: R131.1@76.575,6.225 v1(77.45,6.225)
NetLD7_1: LD7.1 R120.1 | length 17.2
  Top Layer w0.12: v1(11.35,17.475) 12.45,16.375 12.45,9.075 14.25,7.275 LD7.1@14.25,2.6
  Bottom Layer w0.25: v1(11.35,17.475) R120.1@11.35,18.625
NetLD7_2: LD7.2 Q5.3 | length 17.7
  Top Layer w0.12: v1(12.85,17.475) 12.85,9.175 15.75,6.275 LD7.2@15.75,2.6
  Bottom Layer w0.25: Q5.3@12.85,15.875 v1(12.85,17.475)
NetQ2_1: Q2.1 R79.2 R80.2 | length 2.7
  Bottom Layer w0.12: R80.2@84.05,59.55 R79.2@85.15,59.55 85.125,59.575 Q2.1@85.125,61.125
NetQ3_1: Q3.1 R104.2 R105.2 | length 3.2
  Bottom Layer w0.12: R105.2@7.225,29.15 R104.2@8.875,29.15 8.875,27.9 Q3.1@9.1,27.675
NetQ4_1: Q4.1 R106.2 R107.2 | length 3.3
  Bottom Layer w0.12: R107.2@1.972,28.966 3.566,28.966 R106.2@3.6,29 3.6,28.031 4.04,27.591 Q4.1@4.147,27.591
NetQ5_1: Q5.1 R128.2 R129.2 | length 3
  Bottom Layer w0.12: R129.2@13.625,10.75 R128.2@13.625,12.1 13.625,13.5 Q5.1@13.8,13.675
NetR12_1: R12.1 U5.4 | length 2.1
  Top Layer w0.12: R12.1@33.225,88.4 33.231,88.406 33.231,89.559 33.4,89.729 U5.4@33.4,90.475
NetR21_1: R21.1 TP4.1 U22.A5 | length 6
  Top Layer w0.12: R21.1@48.55,52.5 49.1,52.5 v1(49.725,53.125) 49.725,54.375 v1(49.4,54.7)
  Bottom Layer w0.12: TP4.1@48.3,55.925 49.125,55.925 49.4,55.65 v1(49.4,54.7) ; v1(49.725,53.125) U22.A5@50.225,52.625
NetR22_2: R22.2 U22.A4 | length 8.6
  Top Layer w0.12: v1(44.925,53.35) 45.567,52.708 R22.2@45.567,51.805
  Bottom Layer w0.12: v1(44.925,53.35) 45.174,53.599 50.251,53.599 U22.A4@51.225,52.625
NetR23_1: R23.1 U22.A3 | length 1.5
  Top Layer w0.12: R23.1@52.725,51.375 v1(52.725,52.125)
  Bottom Layer w0.12: U22.A3@52.225,52.625 v1(52.725,52.125)
NetR24_2: R24.2 U22.C2 | length 1.7
  Top Layer w0.12: R24.2@53.625,49.175 53.725,49.275 v1(53.725,50.125)
  Bottom Layer w0.12: U22.C2@53.225,50.625 v1(53.725,50.125)
NetR40_2: R40.2 U11.1 | length 1.6
  Top Layer w0.12: R40.2@15.575,18.4 15.75,18.225 16.975,18.225 U11.1@17.05,18.15
NetR42_1: R42.1 U10.F15 | length 2.2
  Top Layer w0.1: U10.F15@65.05,16.1 65.05,16.36 66.015,17.325 66.35,17.325 R42.1@66.35,17.575
NetR43_2: R43.2 U11.3 | length 1.5
  Top Layer w0.12: R43.2@15.65,17.475 15.79,17.335 16.015,17.335 16.2,17.15 U11.3@17.05,17.15
NetR44_1: R44.1 X2.3 | length 1.2
  Top Layer w0.1: 53.175,15.45 R44.1@53.75,15.45
  Top Layer w0.12: X2.3@52.575,15.45 53.175,15.45
NetR44_2: R44.2 U10.G1 | length 1.3
  Top Layer w0.1: R44.2@54.65,15.45 U10.G1@55.95,15.45
NetR45_2: R45.2 X2.1 | length 1.3
  Top Layer w0.12: R45.2@49.65,14.2 X2.1@50.925,14.2
NetR46_2: R46.2 U10.J15 | length 1.5
  Top Layer w0.1: U10.J15@65.05,14.15 65.425,14.15 65.85,13.725 R46.2@66.35,13.725
NetR47_1: R47.1 R48.1 U11.6 | length 4.3
  Top Layer w0.12: U11.6@18.975,16.225 18.975,15.475 19.85,14.6 R47.1@19.85,13.7 R48.1@21.3,13.7
NetR49_2: R49.2 U10.L4 | length 3.7
  Top Layer w0.1: R49.2@54.65,13.25 54.975,13.25 55.725,12.5 57.55,12.5 U10.L4@57.9,12.85
NetR50_1: R50.1 R51.1 U10.N3 | length 3.9
  Top Layer w0.1: R50.1@54.65,12.2 R51.1@54.65,11.125 54.75,11.225 56.925,11.225 U10.N3@57.25,11.55
NetR55_2: R55.2 SW1.1 | length 5.7
  Bottom Layer w0.12: R55.2@69.95,105.5 73.213,105.5 74.015,106.302 SW1.1@74.015,107.575
NetR58_2: R58.2 R60.1 U20.4 | length 2.3
  Bottom Layer w0.12: U20.4@84.175,99.325 85.5,99.325 R58.2@85.6,99.225 85.6,98.409 R60.1@85.591,98.4
NetR59_1: R59.1 R65.2 U19.5 | length 4.3
  Bottom Layer w0.12: R59.1@72.575,99.675 R59.1@72.742,99.508 ; R65.2@72.75,96.075 72.75,97.275 74.175,98.7 U19.5@74.175,99.325 U19.5@73.992,99.508
NetR60_2: R60.2 R66.1 U20.5
NetR64_2: R64.2 R65.1 U19.4 | length 2.5
  Bottom Layer w0.12: R65.1@73.65,96.075 73.775,96.2 R64.2@74.625,96.2 74.441,96.384 74.441,97.185 74.201,97.425 U19.4@74.175,97.425
NetR69_1: R69.1 R70.1 SB50.1 | length 2
  Bottom Layer w0.1: SB50.1@45.8,73.971 R70.1@45.8,74.896 R69.1@46.85,74.896
NetR81_2: R81.2 U23.7 | length 2.2
  Bottom Layer w0.12: U23.7@68.372,44.814 68.45,44.892 68.45,46.225 R81.2@68.726,46.501 ; R81.2@68.727,46.501 68.922,46.696 R81.2@68.922,46.791
NetR82_2: R82.2 R83.1 U23.5 | length 2.3
  Bottom Layer w0.12: R83.1@65.897,45.816 R82.2@66.947,45.816 67.042,45.816 R82.2@67.237,45.621 ; R82.2@67.237,45.62 67.372,45.485 U23.5@67.372,44.814
NetR83_2: R83.2 R84.2 | length 1.1
  Bottom Layer w0.12: R84.2@64.847,46.716 R83.2@65.897,46.716
NetR88_1: R88.1 U24.4 | length 2.9
  Bottom Layer w0.12: U24.4@85,41.85 85,42.1 85.09,42.19 85.35,42.45 R88.1@85.35,44.65
NetR89_1: R89.1 R90.2 | length 1
  Bottom Layer w0.12: R90.2@87.95,42.65 R89.1@87.95,43.675
NetR90_1: R90.1 R91.2 U24.5 | length 2.5
  Bottom Layer w0.12: U24.5@85.75,41.1 85.832,41.182 86.233,41.182 86.676,41.625 R91.2@87.05,41.625 R90.1@87.05,42.65
NetR93_2: R93.2 U24.7 | length 1.4
  Bottom Layer w0.12: U24.7@85.75,40.1 86.665,40.1 86.735,40.03 86.735,39.97 86.93,39.775 R93.2@87.025,39.775
NetR118_2: R118.2 R122.1 U31.6 | length 10.2
  Signal Layer 3 w0.1: v3(62.625,19.325) v3(68.4,19.325)
  Signal Layer 4 w0.1: v3(62.625,19.325) v2(62.625,19.625) ; v3(68.4,19.325) v2(68.6,19.525)
  Bottom Layer w0.1: R122.1@61.025,17.85 62.325,17.85 62.625,18.15 U31.6@62.625,18.975 v2(62.625,19.625) ; v2(68.6,19.525) R118.2@68.6,20.125
NetR119_2: R119.2 U31.7 | length 1.1
  Bottom Layer w0.1: U31.7@63.125,18.975 R119.2@63.125,20.05
NetR121_1: R121.1 R127.2 U32.6 | length 26.5
  Top Layer w0.1: v1(71.475,19.875) 71.475,14.155 72.175,13.455 v1(72.175,12.525)
  Signal Layer 3 w0.09: v3(57.85,19.255) 61.28,19.255 61.62,19.595 65.762,19.595 65.802,19.555 66.483,19.555 66.513,19.585 68.11,19.585 68.4,19.875 v1(71.475,19.875)
  Signal Layer 4 w0.1: v3(57.85,19.255) v2(57.85,19.65)
  Bottom Layer w0.1: R127.2@70.775,12.525 v1(72.175,12.525)
  Bottom Layer w0.12: R121.1@56.3,17.875 57.525,17.875 57.85,18.2 U32.6@57.85,18.975 v2(57.85,19.65)
NetTP5_1: TP5.1 U22.C5 | length 10.9
  Top Layer w0.12: v1(49.475,51) 51.459,51 52.275,51.816 52.275,52.65 53.25,53.625 v1(53.25,55.9)
  Bottom Layer w0.12: v1(49.475,51) 49.85,50.625 U22.C5@50.225,50.625 ; TP5.1@50.85,55.9 v1(53.25,55.9)
NetTP6_1: TP6.1 U22.A2 | length 5.4
  Top Layer w0.12: v1(53.725,53.125) 55.7,55.1 v1(55.7,55.875)
  Bottom Layer w0.12: U22.A2@53.225,52.625 v1(53.725,53.125) ; TP6.1@54.592,55.879 54.596,55.875 v1(55.7,55.875)
NRST: B2.1 B2.2 C28.2 CN3.10 CN9.5 CN11.12 R20.1 R22.1 R117.1 U8.1 U25.R2 U30.5 | length 175.8
  Top Layer w0.1: C28.2@46.65,52.5 46.65,52.975 46.85,53.175 v1(47.55,53.175) ; v1(70.475,23.85) 71.85,22.475 v1(71.85,17.7)
  Top Layer w0.12: R22.1@45.567,50.905 45.762,51.1 45.892,51.1 46.152,51.361 46.152,52.002 46.43,52.28 46.43,52.305 46.625,52.5 C28.2@46.65,52.5 ; R20.1@47.55,52.5 v1(47.55,53.175) ; v1(79.65,80.9) 80.262,80.9 U8.1@80.275,80.887 80.3,80.912 80.3,82.775 80.525,83 B2.1@81.45,83 B2.2@87.05,83 ; CN3.10@87.3,19.935 87.31,19.925 v1(88.1,19.925)
  Signal Layer 3 w0.1: v3(44.398,39.65) 44.775,40.027 44.775,52.555 45.395,53.175 v3(46.35,53.175) ; v3(62.235,22.36) 63.45,23.575 v1(65.975,23.575) 70.2,23.575 v1(70.475,23.85) ; v1(66.9,24.225) 66.9,25.875 66.425,26.35 66.425,32.9 66.928,33.403 66.928,46.903 67.25,47.225
  Signal Layer 3 w0.12: v1(47.55,53.175) v1(47.55,57.2) ; v3(50.1,22.225) 56.315,22.225 58.315,24.225 v1(66.9,24.225) ; 67.25,47.225 67.25,50.475 67.75,50.975 67.75,57.354 CN9.5@69.04,58.644 ; v1(71.85,17.7) 73.635,19.485 87.66,19.485 v1(88.1,19.925)
  Signal Layer 4 w0.1: v2(44.05,39.65) v3(44.398,39.65) ; v3(46.35,53.175) v2(46.698,53.175) ; v2(49.875,22) v3(50.1,22.225) ; v2(61.975,22.125) 61.987,22.125 62.222,22.36 v3(62.235,22.36)
  Bottom Layer w0.1: U25.R2@43.7,39.65 v2(44.05,39.65) ; v2(46.698,53.175) v1(47.55,53.175) ; v1(65.975,23.575) U30.5@66.9,23.575 v1(66.9,24.225)
  Bottom Layer w0.12: v1(47.55,57.2) 47.56,57.21 67.606,57.21 75.93,65.534 75.93,78.83 78,80.9 v1(79.65,80.9) ; R117.1@49.075,22.05 49.125,22 v2(49.875,22) ; CN11.12@61.965,23.793 61.975,23.783 v2(61.975,22.125)
OCTOSPIM_P1.CLK: U22.B2 U25.L1 | length 23.5
  Bottom Layer w0.12: U25.L1@40.5,40.45 40.5,42.629 40.721,42.85 40.9,42.85 41.125,43.075 41.125,43.375 40.925,43.575 40.925,43.931 41.25,44.256 41.25,50.75 41.95,51.45 49.625,51.45 49.95,51.125 52.725,51.125 U22.B2@53.225,51.625
OCTOSPIM_P1.DQS: U22.C3 U25.P3 | length 24.1
  Bottom Layer w0.1: U25.P3@42.9,38.85 43.2,39.15 44.625,39.15 45.575,40.1
  Bottom Layer w0.12: 45.575,40.1 47.6,42.125 47.6,43.62 48.08,44.1 52.375,44.1 55.475,47.2 55.475,50.825 55.175,51.125 53.15,51.125 52.65,50.625 U22.C3@52.225,50.625
OCTOSPIM_P1.IO0: U22.D3 U25.M3 | length 23.6
  Bottom Layer w0.1: U25.M3@41.3,38.85 41.8,39.35 41.8,41.43 42.07,41.7
  Bottom Layer w0.12: 42.07,41.7 43.475,41.7 43.675,41.9 43.675,46.275 45.425,48.025 45.635,48.025 45.95,48.025 46.055,48.13 46.055,48.494 46.16,48.599 46.37,48.599 46.475,48.494 46.475,48.025 46.475,47.632 46.58,47.527 46.79,47.527 46.895,47.632 46.895,48.025 46.895,48.494 47,48.599 47.21,48.599 47.315,48.494 47.315,48.025 47.315,47.622 47.42,47.517 47.63,47.517 47.735,47.622 47.735,47.92 47.84,48.025 48.175,48.025 48.5,48.025 48.785,47.74 51.165,47.74 51.675,48.25 51.675,49.075 U22.D3@52.225,49.625
OCTOSPIM_P1.IO1: U22.D2 U25.L4 | length 24.1
  Bottom Layer w0.1: U25.L4@40.5,38.05 41,38.55 41,42 41.103,42.103
  Bottom Layer w0.12: 41.103,42.103 42.225,43.225 42.225,49.675 43.075,50.525 46.435,50.525 46.95,50.01 52.84,50.01 U22.D2@53.225,49.625
OCTOSPIM_P1.IO2: U22.C4 U25.L3 | length 23.7
  Bottom Layer w0.1: U25.L3@40.5,38.85 40.8,39.15 40.8,42.275
  Bottom Layer w0.12: 40.8,42.275 41.85,43.325 41.85,44 41.725,44.125 41.725,49.9 42.8,50.975 46.475,50.975 46.646,50.975 46.961,50.975 47.066,50.87 47.066,50.54 47.171,50.435 47.381,50.435 47.486,50.54 47.486,50.87 47.591,50.975 47.801,50.975 47.906,50.87 47.906,50.54 48.011,50.435 48.221,50.435 48.326,50.54 48.326,50.87 48.431,50.975 48.746,50.975 48.956,50.975 49.691,50.24 50.84,50.24 U22.C4@51.225,50.625
OCTOSPIM_P1.IO3: U22.D4 U25.M2 | length 23.3
  Bottom Layer w0.1: U25.M2@41.3,39.65 41.6,39.95 41.6,41.675
  Bottom Layer w0.12: 41.6,41.675 41.95,42.025 42.9,42.025 43.075,42.2 43.075,48.75 43.375,49.05 43.425,49.05 43.53,49.05 43.635,48.945 43.635,48.115 43.74,48.01 43.95,48.01 44.055,48.115 44.055,49.05 44.055,49.06 44.16,49.165 44.37,49.165 44.475,49.06 44.475,49.05 44.475,48.115 44.58,48.01 44.79,48.01 44.895,48.115 44.895,48.945 45,49.05 45.175,49.05 47.425,49.05 48,48.475 49.45,48.475 50.025,49.05 50.65,49.05 U22.D4@51.225,49.625
OCTOSPIM_P1.IO4: U22.D5 U25.M1 | length 22.7
  Bottom Layer w0.12: U25.M1@41.3,40.45 41.3,41.825 41.825,42.35 42.3,42.35 42.625,42.675 42.625,45.925 42.625,49.425 42.825,49.625 43.035,49.625 43.35,49.625 43.455,49.73 43.455,50.035 43.56,50.14 43.77,50.14 43.875,50.035 43.875,49.73 43.98,49.625 44.19,49.625 44.295,49.73 44.295,50.035 44.4,50.14 44.61,50.14 44.715,50.035 44.715,49.73 44.82,49.625 45.03,49.625 45.135,49.73 45.135,50.035 45.24,50.14 45.45,50.14 45.555,50.035 45.555,49.73 45.66,49.625 45.87,49.625 45.975,49.73 45.975,50.035 46.08,50.14 46.29,50.14 46.395,50.035 46.395,49.73 46.5,49.625 46.6,49.625 46.775,49.625 46.9,49.5 47.775,49.5 47.88,49.5 47.985,49.395 47.985,49.115 48.09,49.01 48.3,49.01 48.405,49.115 48.405,49.5 48.405,49.535 48.51,49.64 48.72,49.64 48.825,49.535 48.825,49.5 48.825,49.115 48.93,49.01 49.14,49.01 49.245,49.115 49.245,49.5 49.245,49.535 49.35,49.64 49.56,49.64 49.665,49.535 49.7,49.5 49.875,49.5 50.1,49.5 U22.D5@50.225,49.625
OCTOSPIM_P1.IO5: U22.E3 U25.P1 | length 22.3
  Bottom Layer w0.12: U25.P1@42.9,40.45 44.25,41.8 44.25,46.025 45.3,47.075 47.25,47.075 47.355,47.075 47.46,46.97 47.46,46.408 47.565,46.303 47.775,46.303 47.88,46.408 47.88,47.075 47.88,47.127 47.985,47.232 48.195,47.232 48.3,47.127 48.3,47.075 48.3,46.408 48.405,46.303 48.615,46.303 48.72,46.408 48.72,47.075 48.72,47.127 48.825,47.232 49.035,47.232 49.14,47.127 49.14,47.075 49.14,46.408 49.245,46.303 49.455,46.303 49.56,46.408 49.56,47.075 49.56,47.127 49.665,47.232 49.875,47.232 49.98,47.127 49.98,47.075 49.98,46.408 50.085,46.303 50.295,46.303 50.4,46.408 50.4,47.075 50.4,47.127 50.505,47.232 50.715,47.232 50.82,47.127 50.82,47.159 ; 50.82,47.16 50.905,47.075 51.55,47.075 51.925,47.075 52.225,47.375 U22.E3@52.225,48.625
OCTOSPIM_P1.IO6: U22.E2 U25.N3 | length 24.3
  Bottom Layer w0.12: U25.N3@42.1,38.85 42.525,39.275 42.525,39.8 42.775,40.05 44.3,40.05 44.775,40.525 44.775,45.575 45,45.8 45.175,45.8 45.23,45.8 45.335,45.695 45.335,45.235 45.44,45.13 45.65,45.13 45.755,45.235 45.755,45.8 45.755,46.365 45.86,46.47 46.07,46.47 46.175,46.365 46.175,45.8 46.175,45.235 46.28,45.13 46.49,45.13 46.595,45.235 46.595,45.8 46.595,46.365 46.7,46.47 46.91,46.47 47.015,46.365 47.015,45.905 47.12,45.8 47.225,45.8 52.3,45.8 53.225,46.725 U22.E2@53.225,48.625
OCTOSPIM_P1.IO7: U22.E1 U25.P2 | length 22.9
  Bottom Layer w0.1: U25.P2@42.9,39.65 43.2,39.35 44.15,39.35 45.025,40.225
  Bottom Layer w0.12: 45.025,40.225 47.125,42.325 47.125,44.675 47.325,44.875 48.03,44.875 48.135,44.98 48.135,45.167 48.24,45.272 48.45,45.272 48.555,45.167 48.555,44.875 48.555,44.583 48.66,44.478 48.87,44.478 48.975,44.583 48.975,44.875 48.975,45.167 49.08,45.272 49.29,45.272 49.395,45.167 49.395,44.875 49.395,44.583 49.5,44.478 49.71,44.478 49.815,44.583 49.815,44.875 49.815,45.167 49.92,45.272 50.13,45.272 50.235,45.167 50.235,44.875 50.235,44.583 50.34,44.478 50.55,44.478 50.655,44.583 50.655,44.875 50.655,45.167 50.76,45.272 50.97,45.272 51.075,45.167 51.075,44.875 51.075,44.583 51.18,44.478 51.39,44.478 51.495,44.583 51.495,44.77 51.6,44.875 51.915,44.875 52.125,44.875 54.225,46.975 U22.E1@54.225,48.625
OCTOSPIM_P1.NCS: R23.2 R24.1 R25.1 U25.M4 | length 23
  Top Layer w0.12: v1(44.125,47.425) 47.75,47.425 49.5,49.175 R24.1@52.725,49.175 ; R25.1@52.725,47.775 R24.1@52.725,49.175 ; R23.2@52.725,50.475 R24.1@52.725,49.175
  Signal Layer 3 w0.09: v3(42.45,38.45) 43.525,39.525 43.525,46.825 v1(44.125,47.425)
  Signal Layer 4 w0.1: v2(42,38.45) v3(42.45,38.45)
  Bottom Layer w0.1: U25.M4@41.3,38.05 41.7,38.45 v2(42,38.45)
OPAMP1_VINM: TP20.1 U25.R3 | length 19.8
  Bottom Layer w0.1: U25.R3@43.7,38.85 45,38.85 48.025,41.875 48.025,43.375 48.275,43.625 53.905,43.625 56.825,46.545 TP20.1@56.825,49.2
OPAMP2_VINM: TP19.1 U25.N5 | length 22.9
  Bottom Layer w0.1: U25.N5@42.1,37.25 42.6,37.75 45.4,37.75 50.1,42.45 53.725,42.45 59.275,48 TP19.1@59.275,49.225
PA0: CN9.21 U25.N4 | length 69.4
  Signal Layer 2 w0.12: v1(47.5,80.05) 48.076,79.474 58.024,79.474 58.355,79.805 v1(60.939,79.805)
  Signal Layer 3 w0.12: v1(47.5,80.05) 47.5,72.6 48.55,71.55 48.55,45.925 48.55,42.99 v3(48.665,42.875)
  Signal Layer 4 w0.1: v2(48.317,42.875) v3(48.665,42.875)
  Bottom Layer w0.1: U25.N4@42.1,38.05 42.4,38.35 43.15,38.35 43.35,38.55 45.075,38.55 48.317,41.792 v2(48.317,42.875)
  Bottom Layer w0.12: v1(60.939,79.805) 61.334,80.2 67.804,80.2 CN9.21@69.04,78.964
PA3: CN10.32 U25.P4 | length 74.6
  Signal Layer 3 w0.12: v1(47.025,80.8) 47.025,78.393 47.28,78.138 47.28,72.346 48.155,71.471 48.155,45.925 48.155,42.62 v3(48.475,42.3)
  Signal Layer 4 w0.1: v3(48.475,42.3) v2(48.7,42.075)
  Bottom Layer w0.1: U25.P4@42.9,38.05 43.225,38.05 43.525,38.35 45.258,38.35 48.7,41.792 v2(48.7,42.075)
  Bottom Layer w0.12: CN10.32@20.78,84.044 21.999,82.825 25.125,82.825 26.8,81.15 32.578,81.15 32.928,80.8 v1(47.025,80.8)
PA4: CN9.25 U25.M5 | length 86
  Top Layer w0.12: v1(41.575,90.95) 41.575,89 42.625,87.95 62.31,87.95 64.899,85.361 67.723,85.361 CN9.25@69.04,84.044
  Signal Layer 3 w0.09: v3(41.475,37.425) 41.448,37.453 41.448,45.897 41.448,90.728 41.575,90.855 v1(41.575,90.95) v1@41.548,90.923
  Signal Layer 4 w0.1: v3(41.475,37.425) v2(41.7,37.65)
  Bottom Layer w0.12: U25.M5@41.3,37.25 v2(41.7,37.65)
PA5: SB9.1 U25.R4 | length 70.9
  Top Layer w0.12: v1(73.5,84.35) 73.5,83.7 73.7,83.5 SB9.1@74.25,83.5
  Signal Layer 3 w0.12: v1(73,50.825) 73,83.85 v1(73.5,84.35)
  Bottom Layer w0.1: U25.R4@43.7,38.05 45.333,38.05 49.936,42.653
  Bottom Layer w0.12: 49.936,42.653 50.283,43 53.8,43 58.4,47.6 58.4,49.4 59.325,50.325 72.5,50.325 v1(73,50.825)
PA6: CN9.30 U25.P5 | length 78.1
  Signal Layer 3 w0.09: v3(45.875,37.775) 45.875,41.25 47.15,42.525 47.15,52.125 46.875,52.4 46.875,65.407 46.325,65.957 46.325,90.575 v1(46.9,91.15)
  Signal Layer 4 w0.1: v2(45.65,37.55) v3(45.875,37.775)
  Bottom Layer w0.1: U25.P5@42.9,37.25 43.2,37.55 v2(45.65,37.55)
  Bottom Layer w0.12: v1(46.9,91.15) 48.926,89.124 CN9.30@66.5,89.124
PA7: CN10.18 U25.R5 | length 60.8
  Top Layer w0.12: v1(43.9,65.2) 44.185,65.485 46.76,65.485 v1(47.4,66.125)
  Signal Layer 3 w0.12: v3(46.613,38.262) 46.613,41.338 47.55,42.275 47.55,45.925 47.55,52.307 47.09,52.767 47.09,65.815 v1(47.4,66.125)
  Signal Layer 4 w0.1: v2(46.388,38.037) v3(46.613,38.262)
  Bottom Layer w0.1: U25.R5@43.7,37.25 45.739,37.25 46.388,37.899 v2(46.388,38.037)
  Bottom Layer w0.12: CN10.18@20.78,66.264 22.044,65 23.875,65 25.325,63.55 34.85,63.55 36.5,65.2 v1(43.9,65.2)
PA8: SB59.2 U25.A13 | length 18.3
  Bottom Layer w0.1: 26.98,29.21 29.12,31.35 32,31.35 U25.A13@32.5,30.85
  Bottom Layer w0.12: SB59.2@22.5,21.575 22.5,23.275 22.1,23.675 22.1,27.55 23.76,29.21 26.98,29.21
PA15: SB42.2 SB43.2 U25.A11 | length 9.7
  Top Layer w0.12: v1(25.65,30.275) 25.65,29.6 SB42.2@25.525,29.475 SB43.2@26.65,29.475
  Bottom Layer w0.1: v1(25.65,30.275) 26.76,30.275 28.485,32 31.725,32 32.075,32.35 32.25,32.35 32.4,32.35 U25.A11@32.5,32.45
PB0: CN9.22 U25.N6 | length 63.3
  Signal Layer 2 w0.09: v1(49.4,76.775) v1(60.725,76.775)
  Signal Layer 3 w0.09: v3(47.463,38.975) 47.463,40.538 48.95,42.025 48.95,46.66 48.885,46.725 48.885,68.81 49.4,69.325 v1(49.4,76.775)
  Signal Layer 4 w0.1: v2(47.238,38.75) v3(47.463,38.975)
  Bottom Layer w0.1: U25.N6@42.1,36.45 42.6,36.95 45.775,36.95 47.238,38.413 v2(47.238,38.75)
  Bottom Layer w0.12: v1(60.725,76.775) 61.975,76.775 64.164,78.964 CN9.22@66.5,78.964
PB1: CN9.28 U25.M6 | length 80.1
  Top Layer w0.12: v1(42,89.719) 43.345,88.375 64.709,88.375 CN9.28@66.5,86.584
  Signal Layer 3 w0.09: v3(41.475,36.625) 41.862,37.012 41.862,40.488 41.7,40.65 41.7,58.85 41.8,58.95 41.8,88.85 42,89.05 v1(42,89.719)
  Signal Layer 4 w0.1: v3(41.475,36.625) v2(41.7,36.85)
  Bottom Layer w0.12: U25.M6@41.3,36.45 v2(41.7,36.85)
PB2: CN9.19 U25.R7 | length 64.2
  Signal Layer 3 w0.12: v1(70.55,76.425) 71.349,76.425 72.55,75.224 72.55,51.35 72.175,50.975 v1(72.175,49.375)
  Bottom Layer w0.1: U25.R7@43.7,35.65 45.975,35.65 47.15,36.825 47.753,36.825 49.353,38.425 49.644,38.425
  Bottom Layer w0.12: 49.644,38.425 51.475,38.425 62.425,49.375 v1(72.175,49.375) ; CN9.19@69.04,76.424 CN9.19@69.04,76.424 v1(70.55,76.425)
PB3: SB33.2 SB34.2 U25.E7 | length 20.2
  Top Layer w0.12: v1(51.25,37.75) SB33.2@52.038,37.75 SB34.2@52.038,36.625
  Signal Layer 3 w0.09: v3(35.525,35.825) 36.075,35.825 36.275,35.625 41.2,35.625 41.45,35.375 44.775,35.375 46.075,36.675 v3@47.45,36.675
  Signal Layer 4 w0.1: v2(35.3,36.05) v3(35.525,35.825) ; v2(47.45,36.325) v3(47.45,36.673)
  Bottom Layer w0.12: v2(35.3,36.05) U25.E7@35.7,35.65 ; v2@47.485,36.36 v2(47.45,36.325) 47.937,36.325 48.012,36.4 48.4,36.4 49.75,37.75 v1(51.25,37.75)
PB4: CN9.8 U25.D6 | length 52
  Signal Layer 3 w0.09: v3(34.725,36.625) 34.9,36.45 41.125,36.45 41.687,35.888 44.363,35.888 45.423,36.948 48.025,36.948 v3(48.127,37.05) ; v3(63.6,49.124) 63.775,49.299 63.775,58.459 63.903,58.587 63.935,58.619 63.935,58.757 63.635,59.056 63.635,59.194 63.773,59.332 63.911,59.332 64.47,58.773 64.608,58.773 64.746,58.91 64.746,59.048 64.215,59.58 64.215,59.718 64.352,59.856 64.49,59.856 64.9,59.446 65.038,59.446 65.176,59.584 65.176,59.722 65.176,59.86 65.624,60.308 CN9.8@66.5,61.184
  Signal Layer 4 w0.1: v2(34.5,36.85) v3(34.725,36.625) ; v3(48.127,37.05) v2(48.475,37.05) ; v2(63.6,48.777) v3(63.6,49.124)
  Bottom Layer w0.12: v2(34.5,36.85) U25.D6@34.9,36.45 ; v2(48.475,37.05) 49.56,38.135 51.86,38.135 62.075,48.35 63.173,48.35 v2(63.6,48.777)
PB10: SB14.2 SB48.2 U25.N12 | length 82.1
  Top Layer w0.12: SB14.2@51.55,75.496 51.55,73 v1(51.825,72.725)
  Signal Layer 3 w0.09: v3(42.275,31.475) 43.6,30.15 43.925,30.15 45.375,28.7 48.3,28.7 49.605,30.005 54.33,30.005 55.375,31.05 55.375,34.925 55.975,35.525 55.975,43.478 55.105,44.348 55.105,50.62 54.592,51.133 54.592,71.167 v1(55.1,71.675) 55.5,72.075 55.5,75.353 57.704,77.556 60.906,77.556 61.825,78.475 v1(61.825,82.15)
  Signal Layer 4 w0.1: v3(42.275,31.475) v2(42.5,31.25)
  Bottom Layer w0.12: U25.N12@42.1,31.65 v2(42.5,31.25) ; v1(51.825,72.725) 54.05,72.725 v1(55.1,71.675) ; v1(61.825,82.15) 64.313,82.15 64.337,82.174 64.424,82.174 SB48.2@64.45,82.2
PB11: CN9.24 U25.M10 | length 73.5
  Signal Layer 3 w0.09: v3(41.475,33.075) 44.967,33.075 45.275,33.075 45.65,33.45 51.8,33.45 53.45,31.8 54.448,31.8 54.675,32.027 54.675,32.33 54.525,32.48 54.525,35 53.775,35.75 53.775,42.475 54.315,43.015 54.315,74.988 59.527,80.2 v1(60.125,80.2)
  Signal Layer 4 w0.1: v3(41.475,33.075) v2(41.7,32.85)
  Bottom Layer w0.12: U25.M10@41.3,33.25 v2(41.7,32.85) ; v1(60.125,80.2) 61.429,81.504 CN9.24@66.5,81.504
